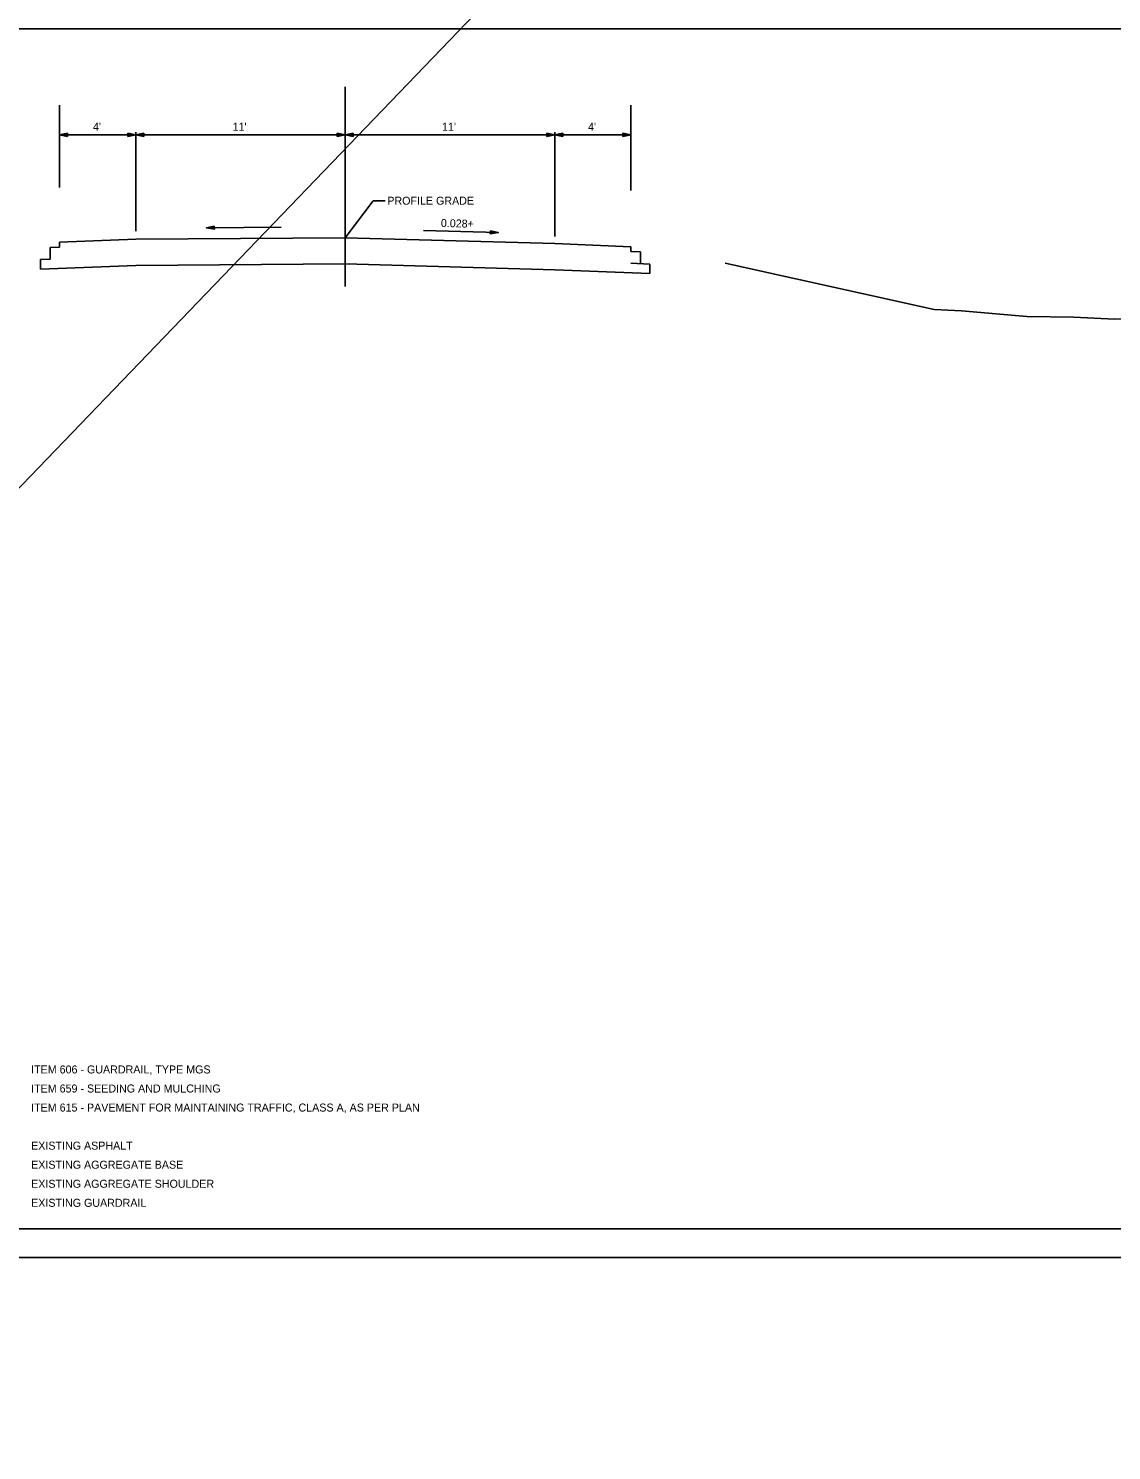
# Model space of a CAD drawing. Extents: x -396 to 156, y -166 to 172.
# Drawn here: x -325.3 to -268.4, y -140.6 to -66 of the extents above; entities that cross this region are included whole.
import ezdxf

# ---------------------------------------------------------------- set-up
doc = ezdxf.new("R2010")
doc.units = 0
for name, color, linetype in [('DT_X_Terrain_Ground_Line', 7, 'Continuous'), ('SH_Border', 7, 'Continuous'), ('SH_Cut_Line', 7, 'Continuous'), ('TX_P_1', 7, 'Continuous'), ('TX_X_1', 7, 'Continuous'), ('XS_P_Finished_Grade', 7, 'Continuous'), ('XS_P_Pavt_Surface', 7, 'Continuous')]:
    doc.layers.add(name, color=color, linetype=linetype)

msp = doc.modelspace()

# ---------------------------------------------------------------- linework, layer by layer
at = {"layer": 'DT_X_Terrain_Ground_Line'}
msp.add_lwpolyline([(-277.72, -80.736), (-276.292, -80.81), (-272.854, -81.102), (-270.39, -81.131), (-268.257, -81.248), (-264.904, -81.172)], dxfattribs=at)
at = {"layer": 'SH_Border'}
msp.add_lwpolyline([(-354.402, -65.996), (-258.402, -65.996), (-258.402, -128.996), (-354.402, -128.996)], close=True, dxfattribs=at)
at = {"layer": 'SH_Cut_Line'}
msp.add_lwpolyline([(-358.902, -130.496), (-256.902, -130.496), (-256.902, -64.496), (-358.902, -64.496)], close=True, dxfattribs=at)
at = {"layer": 'TX_P_1'}
for p, q in [((-323.652, -74.323), (-323.652, -70.001)), ((-293.652, -74.481), (-293.652, -70.001)), ((-323.652, -71.561), (-319.652, -71.561)), ((-323.232, -71.645), (-323.232, -71.477)), ((-320.072, -71.477), (-320.072, -71.645)), ((-319.652, -76.629), (-319.652, -71.432)), ((-319.652, -71.561), (-308.652, -71.561)), ((-319.232, -71.645), (-319.232, -71.477)), ((-309.072, -71.477), (-309.072, -71.645)), ((-309.072, -71.477), (-309.072, -71.645)), ((-308.652, -71.561), (-297.652, -71.561)), ((-308.232, -71.645), (-308.232, -71.477)), ((-298.072, -71.477), (-298.072, -71.645)), ((-298.072, -71.477), (-298.072, -71.645)), ((-297.652, -76.896), (-297.652, -71.432)), ((-297.652, -71.561), (-293.652, -71.561)), ((-297.232, -71.645), (-297.232, -71.477)), ((-294.072, -71.477), (-294.072, -71.645)), ((-308.652, -76.969), (-307.179, -75.024)), ((-307.179, -75.024), (-306.554, -75.024)), ((-315.945, -76.443), (-312.016, -76.416)), ((-315.526, -76.356), (-315.524, -76.524)), ((-300.612, -76.695), (-304.539, -76.585)), ((-301.029, -76.6), (-301.034, -76.767))]:
    msp.add_line(p, q, dxfattribs=at)
for points in [[(-323.232, -71.477), (-323.652, -71.561), (-323.232, -71.645)], [(-320.072, -71.645), (-319.652, -71.561), (-320.072, -71.477)], [(-319.232, -71.477), (-319.652, -71.561), (-319.232, -71.645)], [(-309.072, -71.645), (-308.652, -71.561), (-309.072, -71.477)], [(-309.072, -71.645), (-308.652, -71.561), (-309.072, -71.477)], [(-308.232, -71.477), (-308.652, -71.561), (-308.232, -71.645)], [(-298.072, -71.645), (-297.652, -71.561), (-298.072, -71.477)], [(-298.072, -71.645), (-297.652, -71.561), (-298.072, -71.477)], [(-297.232, -71.477), (-297.652, -71.561), (-297.232, -71.645)], [(-294.072, -71.645), (-293.652, -71.561), (-294.072, -71.477)], [(-315.524, -76.524), (-315.945, -76.443), (-315.526, -76.356)], [(-301.034, -76.767), (-300.612, -76.695), (-301.029, -76.6)]]:
    msp.add_lwpolyline(points, dxfattribs=at)
at = {"layer": 'TX_X_1'}
msp.add_line((-308.652, -79.522), (-308.652, -69.041), dxfattribs=at)
at = {"layer": 'XS_P_Finished_Grade'}
for p, q in [((-88.939, 155.921), (-374.438, -140.631)), ((-288.696, -78.296), (-277.72, -80.736))]:
    msp.add_line(p, q, dxfattribs=at)
at = {"layer": 'XS_P_Pavt_Surface'}
for p, q in [((-323.652, -77.456), (-324.152, -77.476)), ((-324.152, -77.476), (-324.152, -78.098)), ((-319.652, -77.046), (-323.652, -77.206)), ((-323.652, -77.206), (-323.652, -77.456)), ((-308.652, -76.969), (-319.652, -77.046)), ((-308.652, -76.969), (-297.652, -77.277)), ((-297.652, -77.277), (-293.652, -77.437)), ((-293.652, -77.437), (-293.652, -77.687)), ((-324.152, -78.098), (-324.652, -78.118)), ((-324.652, -78.118), (-324.652, -78.618)), ((-308.652, -78.341), (-319.652, -78.418)), ((-308.652, -78.341), (-297.652, -78.649)), ((-293.652, -77.687), (-293.152, -77.707)), ((-293.652, -78.309), (-292.652, -78.349)), ((-293.152, -77.707), (-293.152, -78.329)), ((-292.652, -78.349), (-292.652, -78.849)), ((-319.652, -78.418), (-324.652, -78.618)), ((-297.652, -78.649), (-292.652, -78.849))]:
    msp.add_line(p, q, dxfattribs=at)

# ---------------------------------------------------------------- texts
at = {"layer": 'TX_P_1'}
for s, p in [("4'", (-321.9, -71.351)), ("11'", (-314.567, -71.351)), ("11'", (-303.567, -71.351)), ("4'", (-295.9, -71.351)), ('PROFILE GRADE', (-306.442, -75.234)), ('ITEM 606 - GUARDRAIL, TYPE MGS', (-325.148, -120.836)), ('ITEM 659 - SEEDING AND MULCHING', (-325.148, -121.836)), ('ITEM 615 - PAVEMENT FOR MAINTAINING TRAFFIC, CLASS A, AS PER PLAN', (-325.148, -122.836)), ('EXISTING ASPHALT', (-325.148, -124.836)), ('EXISTING AGGREGATE BASE', (-325.148, -125.836)), ('EXISTING AGGREGATE SHOULDER', (-325.148, -126.836)), ('EXISTING GUARDRAIL', (-325.148, -127.836))]:
    msp.add_text(s, height=0.42, dxfattribs=at).set_placement(p)
msp.add_text('0.028+', height=0.42, rotation=358.39614, dxfattribs=at).set_placement((-303.633, -76.401))

doc.saveas('drawing.dxf')
